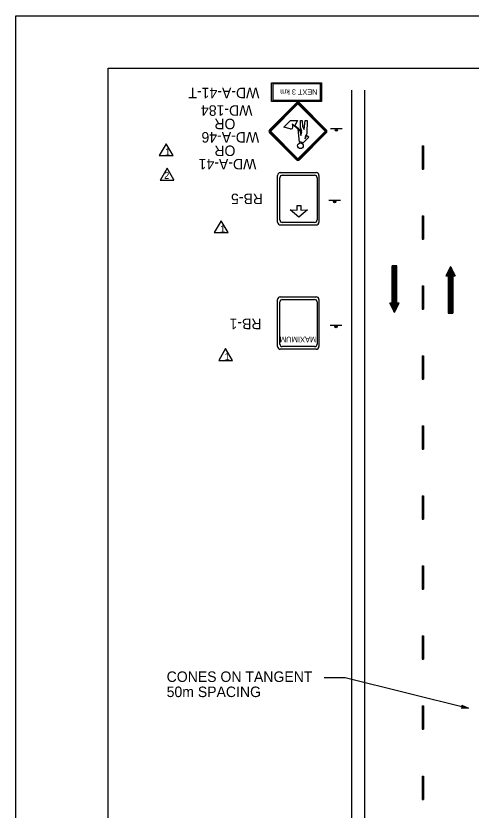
# Model space of a CAD drawing. Extents: x 1371 to 1587, y 163 to 442.
# Drawn here: x 1371 to 1465.4, y 277.8 to 442.4 of the extents above; entities that cross this region are included whole.
import ezdxf

# ---------------------------------------------------------------- set-up
doc = ezdxf.new("R2010")
doc.units = 0
for name, color, linetype in [('Level 1', 7, 'Continuous'), ('Level 10', 7, 'Continuous'), ('Level 44', 7, 'Continuous'), ('Level 5', 7, 'Continuous'), ('Level 60', 7, 'Continuous'), ('Level 63', 7, 'Continuous')]:
    doc.layers.add(name, color=color, linetype=linetype)

msp = doc.modelspace()

# ---------------------------------------------------------------- linework, layer by layer
at = {"layer": 'Level 1'}
for p, q in [((1429.16, 424.38), (1423.58, 418.81)), ((1429.29, 424.26), (1423.71, 418.69)), ((1429.41, 424.14), (1423.83, 418.56)), ((1435.12, 418.56), (1429.54, 424.14)), ((1435.24, 418.68), (1429.67, 424.26)), ((1435.37, 418.81), (1429.79, 424.38)), ((1423.58, 418.18), (1429.16, 412.61)), ((1423.71, 418.31), (1429.28, 412.73)), ((1423.83, 418.43), (1429.41, 412.86)), ((1429.54, 412.86), (1435.12, 418.43)), ((1429.66, 412.73), (1435.24, 418.3)), ((1429.79, 412.61), (1435.37, 418.18)), ((1429.73, 415.05), (1429.75, 415.05))]:
    msp.add_line(p, q, dxfattribs=at)
for points in [[(1427.84, 418.99), (1426.56, 419.37), (1427.94, 420.77), (1429.4, 420.77), (1428.86, 419.71), (1430.27, 418.56), (1429.99, 419.29), (1430.03, 420.77), (1430.38, 420.77), (1430.44, 419.51), (1430.78, 418.87), (1430.96, 420.77), (1431.38, 420.77), (1431.33, 418.04), (1430.89, 416.94), (1431.2, 417.26)], [(1427.84, 418.99), (1426.56, 419.37), (1427.94, 420.77), (1429.4, 420.77), (1428.86, 419.71), (1430.27, 418.56), (1429.99, 419.29), (1430.03, 420.77), (1430.38, 420.77), (1430.44, 419.51), (1430.78, 418.87), (1430.96, 420.77), (1431.38, 420.77), (1431.33, 418.04), (1430.89, 416.94), (1431.2, 417.26)], [(1427.84, 418.99), (1426.56, 419.37), (1427.94, 420.77), (1429.4, 420.77), (1428.86, 419.71), (1430.27, 418.56), (1429.99, 419.29), (1430.03, 420.77), (1430.38, 420.77), (1430.44, 419.51), (1430.78, 418.87)], [(1429.81, 416.22), (1429.53, 418.94), (1429.89, 418.64), (1430.1, 417.62), (1430.27, 418.33), (1428.28, 419.97), (1428.42, 419.61)], [(1429.81, 416.22), (1429.53, 418.94), (1429.89, 418.64), (1430.1, 417.62), (1430.27, 418.33), (1428.28, 419.97), (1428.42, 419.61)], [(1429.81, 416.22), (1429.53, 418.94), (1428.28, 419.97), (1428.42, 419.61)], [(1430.78, 418.87), (1430.96, 420.77), (1431.38, 420.77), (1431.33, 418.04), (1431.22, 417.77), (1431.73, 417.29), (1430.51, 416.04)], [(1431.2, 417.26), (1431.06, 417.37), (1431.22, 417.77), (1431.73, 417.29), (1430.51, 416.04)], [(1431.2, 417.26), (1431.06, 417.37), (1431.22, 417.77), (1431.73, 417.29), (1430.51, 416.04)]]:
    msp.add_lwpolyline(points, dxfattribs=at)
for points in [[(1429.89, 418.64), (1430.1, 417.62), (1430.27, 418.33)], [(1431.2, 417.26), (1431.06, 417.37), (1430.89, 416.94)], [(1402.14, 415.94), (1400.72, 413.47), (1403.56, 413.47)], [(1413.55, 399.97), (1412.13, 397.5), (1414.97, 397.5)], [(1414.46, 373.49), (1413.05, 371.02), (1415.88, 371.02)]]:
    msp.add_lwpolyline(points, close=True, dxfattribs=at)
msp.add_circle((1430, 415.51), 0.591, dxfattribs=at)
msp.add_circle((1430, 415.51), 0.591, dxfattribs=at)
msp.add_circle((1430, 415.51), 0.591, dxfattribs=at)
for centre, radius, start, end in [((1429.48, 424.07), 0.446, 45, 134.9652), ((1429.48, 424.07), 0.27, 45, 134.9652), ((1429.48, 424.07), 0.0948, 45, 134.9652), ((1423.9, 418.5), 0.446, 134.9651, 225), ((1423.9, 418.5), 0.27, 134.9651, 225), ((1423.9, 418.5), 0.0948, 134.9651, 225), ((1427.98, 419.44), 0.475, 253.381, 21.0999), ((1427.98, 419.44), 0.475, 253.381, 21.0999), ((1427.98, 419.44), 0.475, 253.381, 21.0999), ((1435.05, 418.49), 0.0948, 314.965, 45), ((1435.05, 418.49), 0.27, 314.965, 45), ((1435.05, 418.49), 0.446, 314.965, 45), ((1430, 415.51), 0.734, 46.3135, 104.9576), ((1430, 415.51), 0.734, 46.3135, 104.9576), ((1430, 415.51), 0.734, 46.3135, 104.9576), ((1429.47, 412.92), 0.446, 225, 314.9651), ((1429.47, 412.92), 0.27, 225, 314.9651), ((1429.47, 412.92), 0.0948, 225, 314.9651)]:
    msp.add_arc(centre, radius, start, end, dxfattribs=at)
at = {"layer": 'Level 10'}
for p, q in [((1440.59, 427.01), (1440.59, 182.32)), ((1443.31, 427.01), (1443.31, 182.32)), ((1455.26, 415.51), (1455.26, 410.67)), ((1455.26, 415.51), (1455.55, 415.51)), ((1455.33, 415.51), (1455.33, 410.67)), ((1455.41, 415.51), (1455.41, 410.67)), ((1455.48, 415.51), (1455.48, 410.67)), ((1455.55, 415.51), (1455.55, 410.67)), ((1455.26, 410.67), (1455.55, 410.67)), ((1455.26, 400.99), (1455.26, 396.16)), ((1455.26, 400.99), (1455.55, 400.99)), ((1455.33, 400.99), (1455.33, 396.16)), ((1455.41, 400.99), (1455.41, 396.16)), ((1455.48, 400.99), (1455.48, 396.16)), ((1455.55, 400.99), (1455.55, 396.16)), ((1455.26, 396.16), (1455.55, 396.16)), ((1449.05, 382.88), (1449.05, 390.62)), ((1450.02, 390.62), (1449.05, 390.62)), ((1449.05, 381.92), (1449.05, 390.62)), ((1449.17, 381.67), (1449.17, 390.62)), ((1449.29, 381.43), (1449.29, 390.62)), ((1449.41, 381.19), (1449.41, 390.62)), ((1449.54, 380.95), (1449.54, 390.62)), ((1449.66, 381.19), (1449.66, 390.62)), ((1449.78, 381.43), (1449.78, 390.62)), ((1449.9, 381.67), (1449.9, 390.62)), ((1450.02, 382.88), (1450.02, 390.62)), ((1450.02, 381.92), (1450.02, 390.62)), ((1461.14, 390.49), (1460.17, 388.56)), ((1461.02, 390.25), (1461.02, 380.81)), ((1461.14, 390.49), (1461.14, 380.81)), ((1461.14, 390.49), (1462.11, 388.56)), ((1461.26, 390.25), (1461.26, 380.81)), ((1460.17, 388.56), (1460.65, 388.56)), ((1460.29, 388.8), (1460.29, 388.56)), ((1460.41, 389.04), (1460.41, 388.56)), ((1460.53, 389.28), (1460.53, 388.56)), ((1460.65, 389.52), (1460.65, 380.81)), ((1460.65, 388.56), (1460.65, 380.81)), ((1460.77, 389.76), (1460.77, 380.81)), ((1460.89, 390.01), (1460.89, 380.81)), ((1461.38, 390.01), (1461.38, 380.81)), ((1461.5, 389.76), (1461.5, 380.81)), ((1461.62, 389.52), (1461.62, 380.81)), ((1461.62, 388.56), (1461.62, 380.81)), ((1461.62, 388.56), (1462.11, 388.56)), ((1461.74, 389.28), (1461.74, 388.56)), ((1461.86, 389.04), (1461.86, 388.56)), ((1461.98, 388.8), (1461.98, 388.56)), ((1455.26, 386.48), (1455.26, 381.64)), ((1455.26, 386.48), (1455.55, 386.48)), ((1455.26, 386.48), (1455.26, 381.64)), ((1455.26, 386.48), (1455.55, 386.48)), ((1455.33, 386.48), (1455.33, 381.64)), ((1455.33, 386.48), (1455.33, 381.64)), ((1455.41, 386.48), (1455.41, 381.64)), ((1455.41, 386.48), (1455.41, 381.64)), ((1455.48, 386.48), (1455.48, 381.64)), ((1455.48, 386.48), (1455.48, 381.64)), ((1455.55, 386.48), (1455.55, 381.64)), ((1455.55, 386.48), (1455.55, 381.64)), ((1449.54, 380.95), (1448.57, 382.88)), ((1449.05, 382.88), (1448.57, 382.88)), ((1448.69, 382.64), (1448.69, 382.88)), ((1448.81, 382.4), (1448.81, 382.88)), ((1448.93, 382.16), (1448.93, 382.88)), ((1449.54, 380.95), (1450.5, 382.88)), ((1450.5, 382.88), (1450.02, 382.88)), ((1450.14, 382.16), (1450.14, 382.88)), ((1450.26, 382.4), (1450.26, 382.88)), ((1450.38, 382.64), (1450.38, 382.88)), ((1455.26, 381.64), (1455.55, 381.64)), ((1455.26, 381.64), (1455.55, 381.64)), ((1460.65, 380.81), (1461.62, 380.81)), ((1455.26, 371.97), (1455.26, 367.13)), ((1455.26, 371.97), (1455.55, 371.97)), ((1455.33, 371.97), (1455.33, 367.13)), ((1455.41, 371.97), (1455.41, 367.13)), ((1455.48, 371.97), (1455.48, 367.13)), ((1455.55, 371.97), (1455.55, 367.13)), ((1455.26, 367.13), (1455.55, 367.13)), ((1455.26, 357.45), (1455.26, 352.61)), ((1455.26, 357.45), (1455.55, 357.45)), ((1455.33, 357.45), (1455.33, 352.61)), ((1455.41, 357.45), (1455.41, 352.61)), ((1455.48, 357.45), (1455.48, 352.61)), ((1455.55, 357.45), (1455.55, 352.61)), ((1455.26, 352.61), (1455.55, 352.61)), ((1455.26, 342.94), (1455.26, 338.1)), ((1455.26, 342.94), (1455.55, 342.94)), ((1455.26, 342.94), (1455.26, 338.1)), ((1455.26, 342.94), (1455.55, 342.94)), ((1455.33, 342.94), (1455.33, 338.1)), ((1455.33, 342.94), (1455.33, 338.1)), ((1455.41, 342.94), (1455.41, 338.1)), ((1455.41, 342.94), (1455.41, 338.1)), ((1455.48, 342.94), (1455.48, 338.1)), ((1455.48, 342.94), (1455.48, 338.1)), ((1455.55, 342.94), (1455.55, 338.1)), ((1455.55, 342.94), (1455.55, 338.1)), ((1455.26, 338.1), (1455.55, 338.1)), ((1455.26, 338.1), (1455.55, 338.1)), ((1455.26, 328.42), (1455.26, 323.59)), ((1455.26, 328.42), (1455.55, 328.42)), ((1455.33, 328.42), (1455.33, 323.59)), ((1455.41, 328.42), (1455.41, 323.59)), ((1455.48, 328.42), (1455.48, 323.59)), ((1455.55, 328.42), (1455.55, 323.59)), ((1455.26, 323.59), (1455.55, 323.59)), ((1455.26, 313.91), (1455.26, 309.07)), ((1455.26, 313.91), (1455.55, 313.91)), ((1455.33, 313.91), (1455.33, 309.07)), ((1455.41, 313.91), (1455.41, 309.07)), ((1455.48, 313.91), (1455.48, 309.07)), ((1455.55, 313.91), (1455.55, 309.07)), ((1455.26, 309.07), (1455.55, 309.07)), ((1434.95, 305.3), (1439.3, 305.3)), ((1439.3, 305.3), (1464.85, 298.91)), ((1455.26, 299.4), (1455.26, 294.56)), ((1455.26, 299.4), (1455.55, 299.4)), ((1455.33, 299.4), (1455.33, 294.56)), ((1455.41, 299.4), (1455.41, 294.56)), ((1455.48, 299.4), (1455.48, 294.56)), ((1455.55, 299.4), (1455.55, 294.56)), ((1455.26, 294.56), (1455.55, 294.56)), ((1455.26, 284.88), (1455.26, 280.04)), ((1455.26, 284.88), (1455.55, 284.88)), ((1455.33, 284.88), (1455.33, 280.04)), ((1455.41, 284.88), (1455.41, 280.04)), ((1455.48, 284.88), (1455.48, 280.04)), ((1455.55, 284.88), (1455.55, 280.04)), ((1455.26, 280.04), (1455.55, 280.04))]:
    msp.add_line(p, q, dxfattribs=at)
msp.add_lwpolyline([(1464.85, 298.91), (1463.37, 298.97), (1463.68, 299.2), (1463.52, 299.55)], close=True, dxfattribs=at)
at = {"layer": 'Level 44'}
for p, q in [((1438.69, 419.01), (1436.27, 419.01)), ((1425.82, 409.94), (1433.27, 409.94)), ((1425.24, 399.66), (1425.24, 409.37)), ((1425.72, 400.13), (1425.72, 408.87)), ((1426.24, 409.39), (1432.94, 409.39)), ((1433.46, 408.88), (1433.46, 408.87)), ((1433.46, 408.87), (1433.46, 400.13)), ((1433.84, 409.37), (1433.84, 399.66)), ((1433.84, 409.37), (1433.84, 409.37)), ((1438.29, 404.17), (1435.87, 404.17)), ((1433.27, 399.08), (1425.82, 399.08)), ((1432.94, 399.62), (1426.24, 399.62)), ((1425.24, 373.91), (1425.24, 383.62)), ((1425.82, 384.2), (1433.27, 384.2)), ((1426.24, 383.65), (1432.94, 383.65)), ((1433.14, 383.96), (1433.14, 383.96)), ((1433.23, 383.71), (1433.23, 383.71)), ((1433.84, 383.62), (1433.84, 373.91)), ((1433.84, 383.62), (1433.84, 383.62)), ((1425.72, 374.39), (1425.72, 383.13)), ((1433.46, 383.13), (1433.46, 374.39)), ((1433.46, 383.13), (1433.46, 383.13)), ((1438.62, 378.26), (1436.2, 378.26)), ((1432.94, 373.87), (1426.24, 373.87)), ((1433.27, 373.34), (1425.82, 373.34))]:
    msp.add_line(p, q, dxfattribs=at)
msp.add_lwpolyline([(1431.49, 402.26), (1429.69, 400.74), (1427.89, 402.26), (1429.33, 402.18), (1429.33, 403.14), (1430.05, 403.14), (1430.05, 402.18)], close=True, dxfattribs=at)
for centre, radius in [((1437.47, 418.74), 0.242), ((1437.47, 418.74), 0.121), ((1437.07, 403.9), 0.242), ((1437.07, 403.9), 0.121), ((1437.4, 377.99), 0.242), ((1437.4, 377.99), 0.121)]:
    msp.add_circle(centre, radius, dxfattribs=at)
for centre, radius, start, end in [((1425.82, 409.37), 0.575, 90, 180), ((1433.27, 409.37), 0.575, 360, 90), ((1426.24, 408.88), 0.517, 90, 180), ((1432.94, 408.88), 0.517, 360, 90), ((1426.24, 400.14), 0.517, 180, 270), ((1432.94, 400.14), 0.517, 270, 360), ((1425.82, 399.66), 0.575, 180, 270), ((1433.27, 399.66), 0.575, 270, 360), ((1425.82, 383.62), 0.575, 90, 180), ((1426.24, 383.13), 0.517, 90, 180), ((1432.94, 383.13), 0.517, 360, 90), ((1433.27, 383.62), 0.575, 360, 90), ((1425.82, 373.91), 0.575, 180, 270), ((1426.24, 374.39), 0.517, 180, 270), ((1432.94, 374.39), 0.517, 270, 360), ((1433.27, 373.91), 0.575, 270, 360)]:
    msp.add_arc(centre, radius, start, end, dxfattribs=at)
at = {"layer": 'Level 5'}
for points in [[(1434.36, 424.69), (1424, 424.69), (1424, 428.56), (1434.36, 428.56)], [(1434.09, 424.9), (1424.34, 424.9), (1424.34, 428.39), (1434.09, 428.39)]]:
    msp.add_lwpolyline(points, close=True, dxfattribs=at)
at = {"layer": 'Level 60'}
msp.add_line((1370.95, 442.43), (1370.95, 442.43), dxfattribs=at)
for points in [[(1370.95, 442.43), (1586.95, 442.43), (1586.95, 163.43), (1370.95, 163.43)], [(1390.08, 431.62), (1576.95, 431.62), (1576.95, 174.24), (1390.08, 174.24)]]:
    msp.add_lwpolyline(points, close=True, dxfattribs=at)
at = {"layer": 'Level 63'}
for points in [[(1402.33, 410.85), (1400.94, 408.42)], [(1403.73, 408.42), (1402.33, 410.85)], [(1400.94, 408.42), (1400.91, 408.38), (1403.75, 408.38), (1403.73, 408.42)]]:
    msp.add_lwpolyline(points, dxfattribs=at)

# ---------------------------------------------------------------- texts
at = {"layer": 'Level 1'}
for p in [(1401.91, 413.53), (1413.33, 397.56), (1414.24, 371.07)]:
    msp.add_text('1', height=1.45, rotation=360, dxfattribs=at).set_placement(p)
at = {"layer": 'Level 10'}
for s, p in [('WD-A-41-T', (1421.48, 427.54)), ('WD-184', (1420.04, 423.89)), ('OR ', (1416.5, 421.11)), ('WD-A-46', (1421.44, 418.34)), ('OR', (1416.5, 415.56)), ('WD-A-41', (1420.85, 412.78)), ('RB-5', (1422.22, 405.58)), ('RB-1', (1421.91, 379.67))]:
    msp.add_text(s, height=2.177, rotation=180, dxfattribs=at).set_placement(p)
at = {"layer": 'Level 44'}
for s, height, rotation, p in [('2', 1.45, 360, (1401.71, 408.64)), ('MAXIMUM', 1.139, 180, (1433.32, 375.92))]:
    msp.add_text(s, height=height, rotation=rotation, dxfattribs=at).set_placement(p)
for s, p in [('CONES ON TANGENT', (1402.24, 304.38)), ('50m SPACING', (1402.24, 301.24))]:
    msp.add_text(s, height=2.1771, dxfattribs=at).set_placement(p)
at = {"layer": 'Level 5'}
msp.add_text('NEXT 3 km', height=1.098, rotation=180, dxfattribs=at).set_placement((1433.53, 427.19))

doc.saveas('drawing.dxf')
